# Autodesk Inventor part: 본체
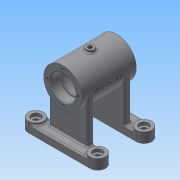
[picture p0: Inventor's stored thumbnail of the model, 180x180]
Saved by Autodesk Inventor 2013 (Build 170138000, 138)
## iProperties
Created: 2015-11
Part Number: 본체
Material: 일반
Document SubType Name: Modeling
Designer: Administrator
Density: 1 g/cm^3
Author: Administrator
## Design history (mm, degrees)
sketch "스케치1"
  geometry: L1 (-40, 40)-(40, 40); L2 (40, -40)-(-40, -40); L3 (50, -30)-(-50, -30); L4 (50, 30)-(-50, 30); L5 (-40, 20)-(40, 20); L6 (-40, -20)-(40, -20); L7 (0, 40)-(0, -40); L8 (-8, 40)-(-8, -40); L9 (8, 40)-(8, -40); L10 (-40, 40)-(-40, 20); L11 (40, 40)-(40, 20); L12 (40, -20)-(40, -40); L13 (-40, -20)-(-40, -40); L14 (-40, 40)-(-40, 20); L15 (40, 20)-(40, 40); A1 r 10 centre (-40, 30) between (-40, 20) and (-50, 30); A2 r 10 centre (40, 30) between (40, 20) and (50, 30); A3 r 10 centre (40, -30) between (40, -20) and (50, -30); A4 r 10 centre (-40, -30) between (-40, -20) and (-50, -30); 3 further points
  constraints: 30 end point, 8 point on circle, 8 point on line, 4 centre point, 4 tangent, 3 midpoint, 3 perpendicular, 1 horizontal, 1 horizontal alignment, 1 parallel, 1 vertical alignment
  dimensions: "d9" = 10 distance between parallel lines of L4 L1; "d10" = 10 distance between parallel lines of L2 L3; "d11" = 20 diameter of A1; "d12" = 20 diameter of A2; "d13" = 20 diameter of A3; "d14" = 20 diameter of A4; "d16" = 8 distance between parallel lines of L8 L7; "d17" = 8 distance between parallel lines of L7 L9; "d18" = 70 distance between parallel lines of L1 L3; "d19" = 40 distance from line of point (0, 0) L1; "d20" = 8 distance from line of point (0, 0) L9; "d21" = 42 distance from line of L4.start L9; "d22" = 42 distance from line of L3.start L9; "d23" = 32 distance from line of L1.end L9; "d24" = 32 distance from line of L2.start L9; "d25" = 48 distance from line of L1.start L9; "d26" = 48 distance from line of A1.centre L9; "d27" = 48 distance from line of L6.start L9; "d28" = 48 distance from line of L2.end L9; "d29" = 58 distance from line of point (-50, 0) L9
extrude "돌출1" new body sketch "스케치1" distance "d30" = 13; taper "d31" = 0 deg
extrude "돌출2" join sketch "스케치1" distance "d32" = 10; taper "d33" = 0 deg
hole "구멍1" diameter "d38" = 6; stored, may be unused: countersink angle "d42" = 82 deg, drill point angle "d44" = 0 deg; dims "d36" = 10, "d37" = 10, "d39" = 6, "d40" = 12, "d41" = 4, "d43" = 8
hole "구멍2" diameter "d47" = 6; stored, may be unused: countersink angle "d51" = 82 deg, drill point angle "d53" = 0 deg; dims "d45" = 10, "d46" = 10, "d48" = 6, "d49" = 12, "d50" = 4, "d52" = 8
hole "구멍3" diameter "d56" = 6; stored, may be unused: countersink angle "d60" = 82 deg, drill point angle "d62" = 0 deg; dims "d54" = 10, "d55" = 10, "d57" = 6, "d58" = 12, "d59" = 4, "d61" = 8
hole "구멍4" diameter "d65" = 6; stored, may be unused: countersink angle "d69" = 82 deg, drill point angle "d71" = 0 deg; dims "d63" = 10, "d64" = 10, "d66" = 6, "d67" = 12, "d68" = 4, "d70" = 8
chamfer "모따기1" distance "d72" = 0.3; stored, may be unused: second distance "d73" = 2, angle "d74" = 45 deg
sketch "스케치2"
  geometry: 1 further point
sketch "스케치3"
  geometry: L1 (40, 0)-(-40, 0) reference; C1 r 25 at (0, 68); 2 further points
  constraints: 1 centre point, 1 midpoint, 1 vertical alignment
  dimensions: "d75" = 50 diameter of C1; "d76" = 68 distance from line of C1.centre L1
extrude "돌출4" join sketch "스케치3" stored distance "d77" = 70; taper "d78" = 0 deg
node "작업 평면2"
hole "구멍5" diameter "d85" = 28; stored, may be unused: countersink angle "d89" = 82 deg, drill point angle "d91" = 0 deg; dims "d83" = 10, "d84" = 10, "d86" = 6, "d87" = 32, "d88" = 12, "d90" = 2
hole "구멍6" diameter "d94" = 28; stored, may be unused: countersink angle "d98" = 82 deg, drill point angle "d100" = 0 deg; dims "d92" = 10, "d93" = 10, "d95" = 6, "d96" = 32, "d97" = 12, "d99" = 2
chamfer "모따기2" distance "d103" = 1; stored, may be unused: second distance "d104" = 2, angle "d105" = 45 deg
node "작업 평면3"
sketch "스케치5"
  geometry: L1 (-40, -40)-(40, -40) reference; L2 (40, -20)-(-40, -20) reference; L3 (-25, -35)-(25, -35) reference; C1 r 5 at (0, 0); A1 r 10 centre (-40, -30) between (-40, -40) and (-40, -20) reference; A2 r 10 centre (40, -30) between (40, -20) and (40, -40) reference; 1 further point
  constraints: 1 centre point, 1 coincident
  dimensions: "d107" = 10 diameter of C1
  node "투영된 루프2"
sketch "스케치6"
  geometry: 1 further point
extrude "돌출6" join sketch "스케치5" distance "d108" = 7; taper "d109" = 0 deg
hole "구멍7" diameter "d112" = 5.188; stored, may be unused: countersink angle "d116" = 82 deg, drill point angle "d118" = 0 deg; dims "d110" = 10, "d111" = 10, "d113" = 20, "d114" = 12, "d115" = 4, "d117" = 30
fillet "모깎기3" dims "d119" = 2
sketch "스케치7"
  geometry: L1 (-40, 68)-(40, 68) reference; C1 r 25 at (0, 0) reference; 2 further points
  dimensions: "d120" = 68 distance from line of point (-20, 0) L1; "d121" = 20 distance of point (-20, 0) C1.centre
hole "구멍8" sketch "스케치7" at (-20, 0) diameter "d122" = 3.242; stored, may be unused: countersink angle "d126" = 82 deg, drill point angle "d128" = 118 deg; dims "d123" = 8, "d124" = 12, "d125" = 4, "d127" = 10
node "작업 평면4"
sketch "스케치8"
  geometry: 1 further point
sketch "스케치9"
  geometry: L1 (80, -40)-(0, -40) reference; L2 (0, -60)-(80, -60) reference; L3 (80, -40)-(0, -40) reference; L4 (80, 0)-(0, 0) reference; L5 (0, 20)-(80, 20) reference; L6 (65, 8)-(15, 8); L7 (15, 8)-(15, 0); L8 (15, 0)-(65, 0); L9 (65, 0)-(65, 8); C1 r 3 at (80, -50) reference; C2 r 3 at (0, -50) reference; C3 r 3 at (80, 10) reference; C4 r 3 at (0, 10) reference; A1 r 10 centre (0, -50) between (0, -40) and (0, -60) reference; A2 r 10 centre (80, -50) between (80, -60) and (80, -40) reference; A3 r 10 centre (80, 10) between (80, 0) and (80, 20) reference; A4 r 10 centre (0, 10) between (0, 20) and (0, 0) reference; 3 further points
  constraints: 8 end point, 2 midpoint, 2 parallel, 1 coincident, 1 horizontal, 1 perpendicular
  dimensions: "d133" = 8 distance between parallel lines of L6 L8; "d135" = 50 distance between parallel lines of L7 L9; "d136" = 8 distance between parallel lines of L6 L4
  node "투영된 루프3"
  node "투영된 루프4"
extrude "돌출8" join sketch "스케치9" distance "d139" = 58; taper "d140" = 0 deg
fillet "모깎기2" dims "d102" = 0.3
sketch "스케치10"
  geometry: 1 further point
fillet "모깎기4" dims "d141" = 2
hole "구멍9" diameter "d144" = 28; stored, may be unused: countersink angle "d148" = 82 deg, drill point angle "d150" = 0 deg; dims "d142" = 10, "d143" = 10, "d145" = 8, "d146" = 32, "d147" = 12, "d149" = 2
hole "구멍10" diameter "d153" = 28; stored, may be unused: countersink angle "d157" = 82 deg, drill point angle "d159" = 0 deg; dims "d151" = 10, "d152" = 10, "d154" = 8, "d155" = 32, "d156" = 12, "d158" = 2
sketch "스케치4"
  geometry: C1 r 25 at (0, 68) reference; C2 r 21 at (0, 68); 1 further point
  constraints: 1 centre point, 1 coincident
  dimensions: "d80" = 42 diameter of C2
extrude "돌출5" cut sketch "스케치4" distance "d81" = 42; taper "d82" = 0 deg
hole "구멍11" diameter "d162" = 3.242; stored, may be unused: countersink angle "d166" = 82 deg, drill point angle "d168" = 118 deg; dims "d160" = 10, "d161" = 10, "d163" = 8, "d164" = 32, "d165" = 12, "d167" = 10
hole "구멍12" diameter "d171" = 3.242; stored, may be unused: countersink angle "d175" = 82 deg, drill point angle "d177" = 118 deg; dims "d169" = 10, "d170" = 10, "d172" = 8, "d173" = 32, "d174" = 12, "d176" = 10
hole "구멍13" diameter "d180" = 3.242; stored, may be unused: countersink angle "d184" = 82 deg, drill point angle "d186" = 118 deg; dims "d178" = 10, "d179" = 10, "d181" = 8, "d182" = 32, "d183" = 12, "d185" = 10
hole "구멍14" diameter "d189" = 3.242; stored, may be unused: countersink angle "d193" = 82 deg, drill point angle "d195" = 118 deg; dims "d187" = 10, "d188" = 10, "d190" = 8, "d191" = 32, "d192" = 12, "d194" = 10
node "작업 평면6"
sketch "스케치11"
  geometry: L1 (-19.887, 70.814)-(19.887, 70.814); L2 (19.887, 70.814)-(19.887, 65.186); L3 (19.887, 65.186)-(-19.887, 65.186); L4 (-19.887, 65.186)-(-19.887, 70.814); L5 (-35, 93)-(-35, 43) reference; L6 (35, 93)-(-35, 93) reference; 4 further points
  constraints: 2 midpoint, 1 horizontal alignment, 1 vertical alignment, 2 other
  dimensions: "d197" = 35 distance from line of L5 point (0, 68); "d198" = 25 distance from line of L6 point (0, 68)
feature "엠보싱1" sketch "스케치11" dims "d26" = 48, "d199" = 0.5, "d200" = 0
fillet "모깎기5" dims "d201" = 2
fillet "모깎기6" dims "d202" = 2
node "솔리드1"
mirror "대칭1"
pattern_circular "원형 패턴1" dims angle "d130" = 360 deg
mirror "대칭2"
mirror "대칭4"
node "작업 평면1"
node "투영된 루프1"
node "작업 평면5"
other parameters: "d79" = 21, "d106" = 96, "d196" = -25
